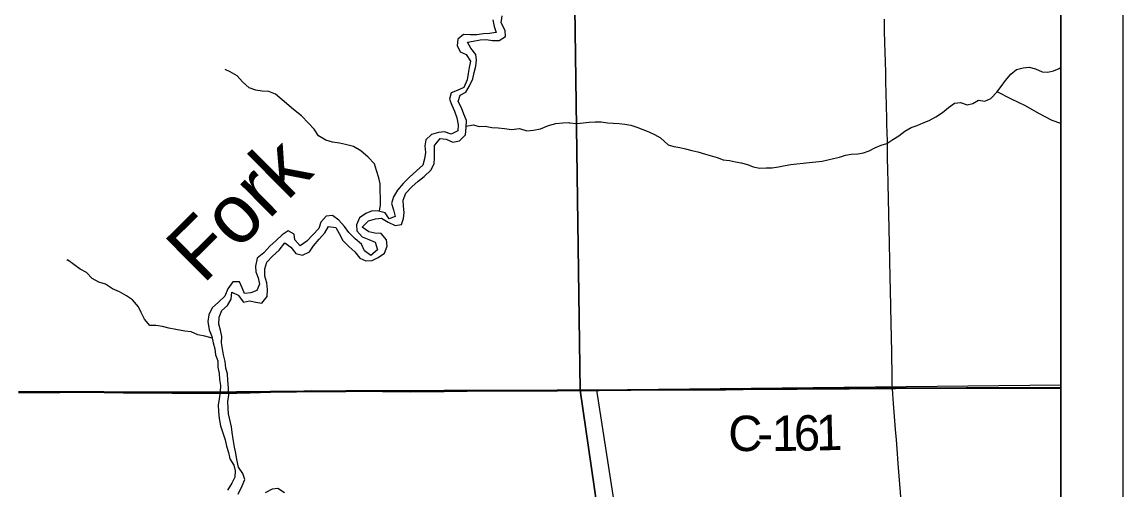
# Model space of a CAD drawing. Extents: x 0 to 34, y 0 to 22.
# Drawn here: x 7.232 to 9, y 16.71 to 17.462 of the extents above; entities that cross this region are included whole.
import ezdxf

# ---------------------------------------------------------------- set-up
doc = ezdxf.new("R2010")
doc.units = 0
for name, color, linetype in [('GM_X_County_Road', 7, 'Continuous'), ('GM_X_County_Road_Text', 7, 'Continuous'), ('GM_X_Interstate_Route', 7, 'Continuous'), ('GM_X_Major_River', 7, 'Continuous'), ('GM_X_Major_River_Text', 7, 'Continuous'), ('GM_X_Minor_River', 7, 'Continuous'), ('GM_X_State_Shield', 7, 'Continuous'), ('GM_X_Township_Road', 7, 'Continuous'), ('SH_Cut_Line', 7, 'Continuous'), ('SH_Data', 7, 'Continuous')]:
    doc.layers.add(name, color=color, linetype=linetype)

msp = doc.modelspace()

# ---------------------------------------------------------------- linework, layer by layer
at = {"layer": 'GM_X_County_Road'}
for points in [[(7.2265, 16.8672), (7.2647, 16.8669), (7.293, 16.8669), (7.332, 16.8673), (7.364, 16.8668), (7.3951, 16.8666), (7.4417, 16.8664), (7.4735, 16.8659), (7.5193, 16.8657), (7.5477, 16.8657), (7.5772, 16.866), (7.5984, 16.8665), (7.6313, 16.8676), (7.673, 16.8683), (7.6972, 16.8685), (7.7319, 16.8688), (7.7524, 16.8688), (7.7875, 16.8689), (7.8111, 16.8685), (7.8559, 16.8679), (7.9102, 16.8688), (7.9472, 16.8691), (7.9869, 16.8694), (8.0288, 16.8694), (8.0919, 16.8698), (8.1287, 16.8701)], [(8.1287, 16.8701), (8.151, 16.8702), (8.1588, 16.8703)], [(8.1588, 16.8703), (8.2098, 16.8705), (8.3123, 16.8712), (8.362, 16.8715), (8.3899, 16.8717), (8.4489, 16.8721), (8.4768, 16.8722), (8.5357, 16.8727), (8.5605, 16.8728), (8.604, 16.8732), (8.6298, 16.8734)], [(8.6298, 16.8734), (8.6348, 16.8735), (8.6564, 16.8737), (8.7212, 16.8737), (8.7491, 16.8738), (8.811, 16.8741), (8.8418, 16.8741), (8.8727, 16.8741), (8.9, 16.874)]]:
    msp.add_lwpolyline(points, dxfattribs=at)
at = {"layer": 'GM_X_Interstate_Route'}
for points in [[(8.1148, 17.8694), (8.1285, 16.8707), (8.1508, 16.8708), (8.2096, 16.871), (8.3121, 16.8717), (8.3618, 16.872), (8.3897, 16.8723), (8.4487, 16.8726), (8.4766, 16.8728), (8.5355, 16.8733), (8.5603, 16.8733), (8.6038, 16.8738), (8.6296, 16.874), (8.6346, 16.874), (8.6562, 16.8742), (8.7209, 16.8742), (8.7489, 16.8743), (8.8108, 16.8746), (8.8416, 16.8747), (8.8725, 16.8747), (8.9, 16.8746), (8.9, 20.9)], [(7.2264, 16.8682), (7.2645, 16.8679), (7.2929, 16.8679), (7.3317, 16.8679), (7.3639, 16.8682), (7.395, 16.8675), (7.4415, 16.8675), (7.4732, 16.8675), (7.5191, 16.8675), (7.5475, 16.8675), (7.5769, 16.8682), (7.598, 16.8682), (7.6311, 16.8685), (7.6727, 16.8688), (7.697, 16.8695), (7.7317, 16.8693), (7.7522, 16.8698), (7.7873, 16.8698), (7.8111, 16.8698), (7.8556, 16.8698), (7.9101, 16.8701), (7.9472, 16.8704), (7.9867, 16.8704), (8.0285, 16.8704), (8.0917, 16.8708), (8.1285, 16.8707), (8.1148, 17.8694)], [(8.2656, 15.9277), (8.1285, 16.8707), (8.0917, 16.8708), (8.0285, 16.8704), (7.9867, 16.8704), (7.9472, 16.8704), (7.9101, 16.8701), (7.8556, 16.8698), (7.8111, 16.8698), (7.7873, 16.8698), (7.7522, 16.8698), (7.7317, 16.8693), (7.697, 16.8695), (7.6727, 16.8688), (7.6311, 16.8685), (7.598, 16.8682), (7.5769, 16.8682), (7.5475, 16.8675), (7.5191, 16.8675), (7.4732, 16.8675), (7.4415, 16.8675), (7.395, 16.8675), (7.3639, 16.8682), (7.3317, 16.8679), (7.2929, 16.8679), (7.2645, 16.8679), (7.2264, 16.8682)], [(8.9, 14.1), (8.9, 16.8746), (8.8725, 16.8747), (8.8416, 16.8747), (8.8108, 16.8746), (8.7489, 16.8743), (8.7209, 16.8742), (8.6562, 16.8742), (8.6346, 16.874), (8.6296, 16.874), (8.6038, 16.8738), (8.5603, 16.8733), (8.5355, 16.8733), (8.4766, 16.8728), (8.4487, 16.8726), (8.3897, 16.8723), (8.3618, 16.872), (8.3121, 16.8717), (8.2096, 16.871), (8.1508, 16.8708), (8.1285, 16.8707), (8.2656, 15.9277)]]:
    msp.add_lwpolyline(points, dxfattribs=at)
at = {"layer": 'GM_X_Major_River'}
for points in [[(7.7095, 17.113), (7.7183, 17.1236), (7.7244, 17.1338), (7.7361, 17.1318), (7.7413, 17.1222), (7.7473, 17.1108), (7.7571, 17.1012), (7.7668, 17.0931), (7.7747, 17.0828), (7.7845, 17.0785), (7.7944, 17.0788), (7.8043, 17.084), (7.8142, 17.0908), (7.8188, 17.1017), (7.8174, 17.1124), (7.8087, 17.1223), (7.7989, 17.1228), (7.7891, 17.1252), (7.7785, 17.1325), (7.7885, 17.1426), (7.7999, 17.1459), (7.8097, 17.147), (7.8203, 17.1404), (7.8312, 17.135), (7.8414, 17.1368), (7.8449, 17.1466), (7.8458, 17.1561), (7.8447, 17.166), (7.844, 17.1759), (7.8487, 17.1872), (7.8582, 17.197), (7.8685, 17.2064), (7.8781, 17.2139), (7.8887, 17.224), (7.8938, 17.2342), (7.8946, 17.244), (7.8948, 17.2638), (7.9036, 17.2747), (7.9134, 17.2738), (7.924, 17.2688), (7.9346, 17.271), (7.9441, 17.2808), (7.9454, 17.2925), (7.9458, 17.3035), (7.9418, 17.3142), (7.9381, 17.3241), (7.9325, 17.3344), (7.9356, 17.3442), (7.9451, 17.3494), (7.9505, 17.3592), (7.9563, 17.3706), (7.9582, 17.3808), (7.961, 17.391), (7.9622, 17.4005), (7.9611, 17.41), (7.9529, 17.4199), (7.9473, 17.4298), (7.9568, 17.4313), (7.9678, 17.4331), (7.9776, 17.4341), (7.9878, 17.4321), (7.9984, 17.4324), (8.0087, 17.4384), (8.008, 17.4482), (8.0017, 17.4608), (8.0033, 17.4718)], [(7.9881, 17.4655), (7.9903, 17.4549), (7.9936, 17.445), (7.983, 17.4435), (7.9732, 17.4429), (7.9625, 17.4411), (7.9523, 17.4412), (7.9413, 17.442), (7.9318, 17.4346), (7.931, 17.4243), (7.9358, 17.414), (7.9456, 17.4098), (7.9523, 17.3991), (7.9504, 17.3888), (7.9484, 17.379), (7.9468, 17.3688), (7.9414, 17.357), (7.9307, 17.3518), (7.9212, 17.3481), (7.9189, 17.3379), (7.9226, 17.3284), (7.9267, 17.3185), (7.9304, 17.3078), (7.9325, 17.2968), (7.9321, 17.2873), (7.9214, 17.2817), (7.9105, 17.2856), (7.901, 17.2846), (7.89, 17.2813), (7.8805, 17.2726), (7.8792, 17.2632), (7.8799, 17.2522), (7.8787, 17.2423), (7.8756, 17.2321), (7.8656, 17.2231), (7.8546, 17.2129), (7.8443, 17.2024), (7.8351, 17.1919), (7.8286, 17.1813), (7.8254, 17.1704), (7.8288, 17.1605), (7.8313, 17.1498), (7.8218, 17.1461), (7.8151, 17.1557), (7.8049, 17.1584), (7.7943, 17.1585), (7.7844, 17.1544), (7.7741, 17.1473), (7.7691, 17.1364), (7.7698, 17.1265), (7.7784, 17.1169), (7.7893, 17.1126), (7.7995, 17.1084), (7.8028, 17.0962), (7.7925, 17.0872), (7.7824, 17.0945), (7.7772, 17.1052), (7.767, 17.1136), (7.7569, 17.124), (7.7498, 17.1335), (7.7408, 17.1439), (7.731, 17.1512), (7.7204, 17.1501), (7.712, 17.1403)], [(7.712, 17.1403), (7.7088, 17.1305), (7.6993, 17.1204), (7.6897, 17.1102), (7.6791, 17.1023), (7.6704, 17.1119), (7.6694, 17.1214), (7.6596, 17.1264), (7.6501, 17.1201), (7.6405, 17.1111), (7.6302, 17.1017), (7.6203, 17.0911), (7.61, 17.0825), (7.6069, 17.07), (7.6075, 17.0605), (7.6112, 17.051), (7.6138, 17.0411), (7.6092, 17.0309), (7.5997, 17.0268), (7.5894, 17.0258), (7.5857, 17.0353), (7.5813, 17.0449), (7.5707, 17.0446), (7.5626, 17.0337), (7.558, 17.0216), (7.5477, 17.0118), (7.5374, 17.0028), (7.5323, 16.9918), (7.5304, 16.9808), (7.5329, 16.9675), (7.537, 16.9569), (7.5392, 16.9466), (7.5417, 16.9371), (7.5432, 16.9276), (7.5465, 16.9181), (7.5468, 16.9078), (7.549, 16.8976), (7.5493, 16.8881), (7.5507, 16.8782), (7.5506, 16.868), (7.5486, 16.857), (7.5474, 16.8467), (7.5477, 16.8365), (7.5487, 16.8251), (7.5509, 16.8133), (7.5542, 16.8038), (7.5583, 16.7908), (7.5608, 16.781), (7.5638, 16.7707), (7.566, 16.7604), (7.5723, 16.7505), (7.5745, 16.741), (7.5741, 16.7311), (7.5694, 16.7213), (7.5621, 16.7104)], [(7.5795, 16.7037), (7.5857, 16.717), (7.5903, 16.7275), (7.587, 16.7371), (7.5799, 16.747), (7.5773, 16.7595), (7.5755, 16.7698), (7.5733, 16.7793), (7.5715, 16.7919), (7.5697, 16.8025), (7.5687, 16.812), (7.5636, 16.8325), (7.5633, 16.842), (7.563, 16.8527), (7.5642, 16.8625), (7.5639, 16.8747), (7.5629, 16.8864), (7.5622, 16.8967), (7.5596, 16.9062), (7.5582, 16.9168), (7.556, 16.9275), (7.5542, 16.937), (7.5528, 16.9465), (7.5529, 16.9571), (7.5507, 16.967), (7.5485, 16.9765), (7.5486, 16.9879), (7.5529, 16.9988), (7.5624, 17.0067), (7.5682, 17.0169), (7.569, 17.0283), (7.5792, 17.0232), (7.5878, 17.0122), (7.5973, 17.014), (7.6075, 17.012), (7.6173, 17.0107), (7.6257, 17.0209), (7.6262, 17.0323), (7.6252, 17.0429), (7.6222, 17.0539), (7.622, 17.0657), (7.6255, 17.0763), (7.6346, 17.0861), (7.6449, 17.0958), (7.6541, 17.1071), (7.6639, 17.1002), (7.6718, 17.0903), (7.6824, 17.0875), (7.6938, 17.0927), (7.7003, 17.1025), (7.7095, 17.113)], [(7.6537, 16.7061), (7.6432, 16.7126), (7.6337, 16.7116), (7.6227, 16.7056)]]:
    msp.add_lwpolyline(points, dxfattribs=at)
at = {"layer": 'GM_X_Minor_River'}
for points in [[(7.8063, 17.158), (7.8076, 17.1686), (7.8077, 17.1789), (7.8071, 17.1906), (7.8071, 17.202), (7.805, 17.2119), (7.8017, 17.2237), (7.798, 17.234), (7.7878, 17.2447), (7.7765, 17.2551), (7.7645, 17.262), (7.7516, 17.2652), (7.7418, 17.2672), (7.7308, 17.2688), (7.7199, 17.2723), (7.7082, 17.2793), (7.7015, 17.2896), (7.6925, 17.2995), (7.6808, 17.3114), (7.6684, 17.3214), (7.65, 17.3371), (7.6391, 17.346), (7.6285, 17.3502), (7.6176, 17.3511), (7.6077, 17.3527), (7.5972, 17.3562), (7.5863, 17.3658), (7.5776, 17.3754), (7.5667, 17.382), (7.5584, 17.3858)], [(8.2574, 17.2761), (8.2696, 17.2646), (8.2787, 17.2618), (8.2886, 17.2605), (8.2977, 17.2585), (8.3075, 17.2557), (8.3174, 17.2537), (8.3295, 17.2497), (8.3484, 17.2441), (8.3579, 17.2406), (8.3681, 17.2393), (8.378, 17.2373), (8.3871, 17.236), (8.397, 17.2332), (8.406, 17.2293), (8.417, 17.2272), (8.4273, 17.2279), (8.4368, 17.2277), (8.4471, 17.2291), (8.4574, 17.2313), (8.4669, 17.233), (8.4761, 17.234), (8.4867, 17.2354), (8.4963, 17.2364), (8.5069, 17.2374), (8.5168, 17.2385), (8.5352, 17.2428), (8.5451, 17.2449), (8.5546, 17.2482), (8.5638, 17.2496), (8.5741, 17.2502), (8.5832, 17.252), (8.5924, 17.2553), (8.6016, 17.2601), (8.6115, 17.2642), (8.6207, 17.2667), (8.6303, 17.2731), (8.6399, 17.279), (8.6499, 17.2869), (8.6599, 17.2924), (8.6698, 17.2957), (8.679, 17.2998), (8.6889, 17.3035), (8.6993, 17.3098), (8.71, 17.3165), (8.72, 17.3244), (8.7293, 17.3315), (8.7392, 17.3325), (8.7498, 17.3289), (8.7589, 17.3311), (8.7681, 17.3366), (8.778, 17.335), (8.788, 17.339), (8.7976, 17.3492), (8.8042, 17.3582), (8.8112, 17.368), (8.8197, 17.3782), (8.8289, 17.3857), (8.8396, 17.3882), (8.8495, 17.3896), (8.8594, 17.3868), (8.87, 17.3817), (8.8791, 17.3812), (8.8886, 17.3833), (8.8978, 17.3874), (8.9, 17.3896)], [(8.9, 17.2992), (8.8863, 17.3039), (8.8648, 17.3148), (8.8433, 17.3273), (8.821, 17.3378), (8.7979, 17.3496)], [(7.9455, 17.2945), (7.9564, 17.2969), (7.9662, 17.2942), (7.9761, 17.2949), (7.9866, 17.2925), (7.9969, 17.292), (8.0067, 17.2908), (8.018, 17.2895), (8.0309, 17.2909), (8.0426, 17.287), (8.0536, 17.2884), (8.0646, 17.2902), (8.0775, 17.2958), (8.0893, 17.2987), (8.1007, 17.3001), (8.1105, 17.3004), (8.1115, 17.3)], [(8.1115, 17.3), (8.1239, 17.2988), (8.1429, 17.301), (8.1528, 17.3014), (8.1623, 17.3014), (8.1722, 17.3002), (8.1813, 17.2994), (8.1909, 17.299), (8.2004, 17.2979), (8.2099, 17.2964), (8.2194, 17.2933), (8.2289, 17.2895), (8.2388, 17.2856), (8.2479, 17.2814), (8.2574, 17.2761)], [(7.5375, 16.9543), (7.526, 16.9574), (7.5147, 16.9598), (7.5041, 16.9644), (7.4935, 16.9656), (7.4795, 16.9684), (7.4682, 16.9704), (7.4576, 16.9732), (7.4474, 16.9744), (7.4375, 16.9745), (7.4289, 16.9849), (7.4237, 16.9952), (7.4192, 17.0047), (7.4099, 17.0158), (7.4001, 17.0223), (7.3888, 17.0289), (7.3775, 17.0332), (7.3662, 17.0409), (7.3556, 17.0444), (7.3447, 17.0502), (7.3356, 17.0598), (7.3258, 17.0652), (7.3153, 17.0725), (7.3055, 17.0798), (7.3044, 17.0791)]]:
    msp.add_lwpolyline(points, dxfattribs=at)
at = {"layer": 'GM_X_State_Shield'}
msp.add_lwpolyline([(8.9, 15.8892), (8.9, 16.8787), (8.1545, 16.8705), (8.2333, 16.3651), (8.2739, 15.9045), (8.6253, 15.8989)], close=True, dxfattribs=at)
at = {"layer": 'GM_X_Township_Road'}
for points in [[(8.6298, 16.8734), (8.6297, 16.8758), (8.6295, 16.8789), (8.6294, 16.882), (8.6294, 16.8912), (8.6286, 16.9321), (8.6278, 16.9783), (8.6266, 17.0311), (8.626, 17.0523), (8.6249, 17.1057), (8.6234, 17.1779), (8.6229, 17.202), (8.6224, 17.2267), (8.6221, 17.2411), (8.6219, 17.2515), (8.6217, 17.2718), (8.6216, 17.2834), (8.6211, 17.2985), (8.6208, 17.3072), (8.6198, 17.3475), (8.6194, 17.3658), (8.6192, 17.3745), (8.6191, 17.379), (8.6186, 17.3998), (8.6183, 17.412), (8.6178, 17.4303), (8.6173, 17.4467), (8.6169, 17.4664)], [(8.644, 16.6932), (8.6392, 16.7528), (8.6373, 16.7765), (8.6361, 16.7908), (8.6348, 16.8077), (8.6327, 16.8356), (8.6316, 16.8493), (8.6304, 16.8642), (8.6298, 16.8734)]]:
    msp.add_lwpolyline(points, dxfattribs=at)
at = {"layer": 'SH_Cut_Line'}
for points in [[(8.9, 14.1), (8.9, 20.9)], [(8.1148, 17.8694), (8.1285, 16.8707), (8.2656, 15.9277)], [(8.2656, 15.9277), (8.1285, 16.8707), (8.1148, 17.8694)]]:
    msp.add_lwpolyline(points, dxfattribs=at)
at = {"layer": 'SH_Data'}
for p, q in [((9, 21), (9, 14)), ((8.9, 20.9), (8.9, 14.1))]:
    msp.add_line(p, q, dxfattribs=at)

# ---------------------------------------------------------------- texts
at = {"layer": 'GM_X_County_Road_Text'}
for s, rotation, p in [('C', 0.2849, (8.3664, 16.7728)), ('1', 0.3807, (8.4365, 16.7731)), ('6', 0.6634, (8.4718, 16.7734)), ('1', 1.4874, (8.5077, 16.7738)), ('-', 0.3065, (8.4131, 16.773))]:
    msp.add_text(s, height=0.0568, rotation=rotation, dxfattribs=at).set_placement(p)
at = {"layer": 'GM_X_Major_River_Text'}
msp.add_text('Fork', height=0.09473, rotation=44.7331, dxfattribs=at).set_placement((7.5228, 17.0395))

doc.saveas('drawing.dxf')
